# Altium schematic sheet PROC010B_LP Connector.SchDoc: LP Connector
size 431 x 279 mm; Date: Not shown in title block; ApprovedBy: Not shown in title block; CheckedBy: Not shown in title block; Author: Not shown in title block; CompanyName: Not shown in title block; DrawnBy: Adrian Ozer; Engineer: Not shown in title block; Organization: Not shown in title block; Address1: Not shown in title block; Address2: Not shown in title block; Address3: Not shown in title block; Address4: Not shown in title block; DocumentNumber: 11; Revision: Use project parameter SCH_Rev; SheetNumber: 11; SheetTotal: 16; PageSetup: Record=PageOptions¦CenterHorizontal=True¦CenterVertical=True¦PrintScale=1.00¦XCorrection=1.00¦YCorrection=1.00¦PrintKind=0¦BorderSize=5000000¦LeftOffset=0¦BottomOffset=0¦Orientation=2¦PaperLength=1000¦PaperWidth=1000¦Scale=100¦PaperSource=15¦PrintQuality=600¦MediaType=1¦DitherType=10¦PaperKind=Letter¦PrintScaleMode=1
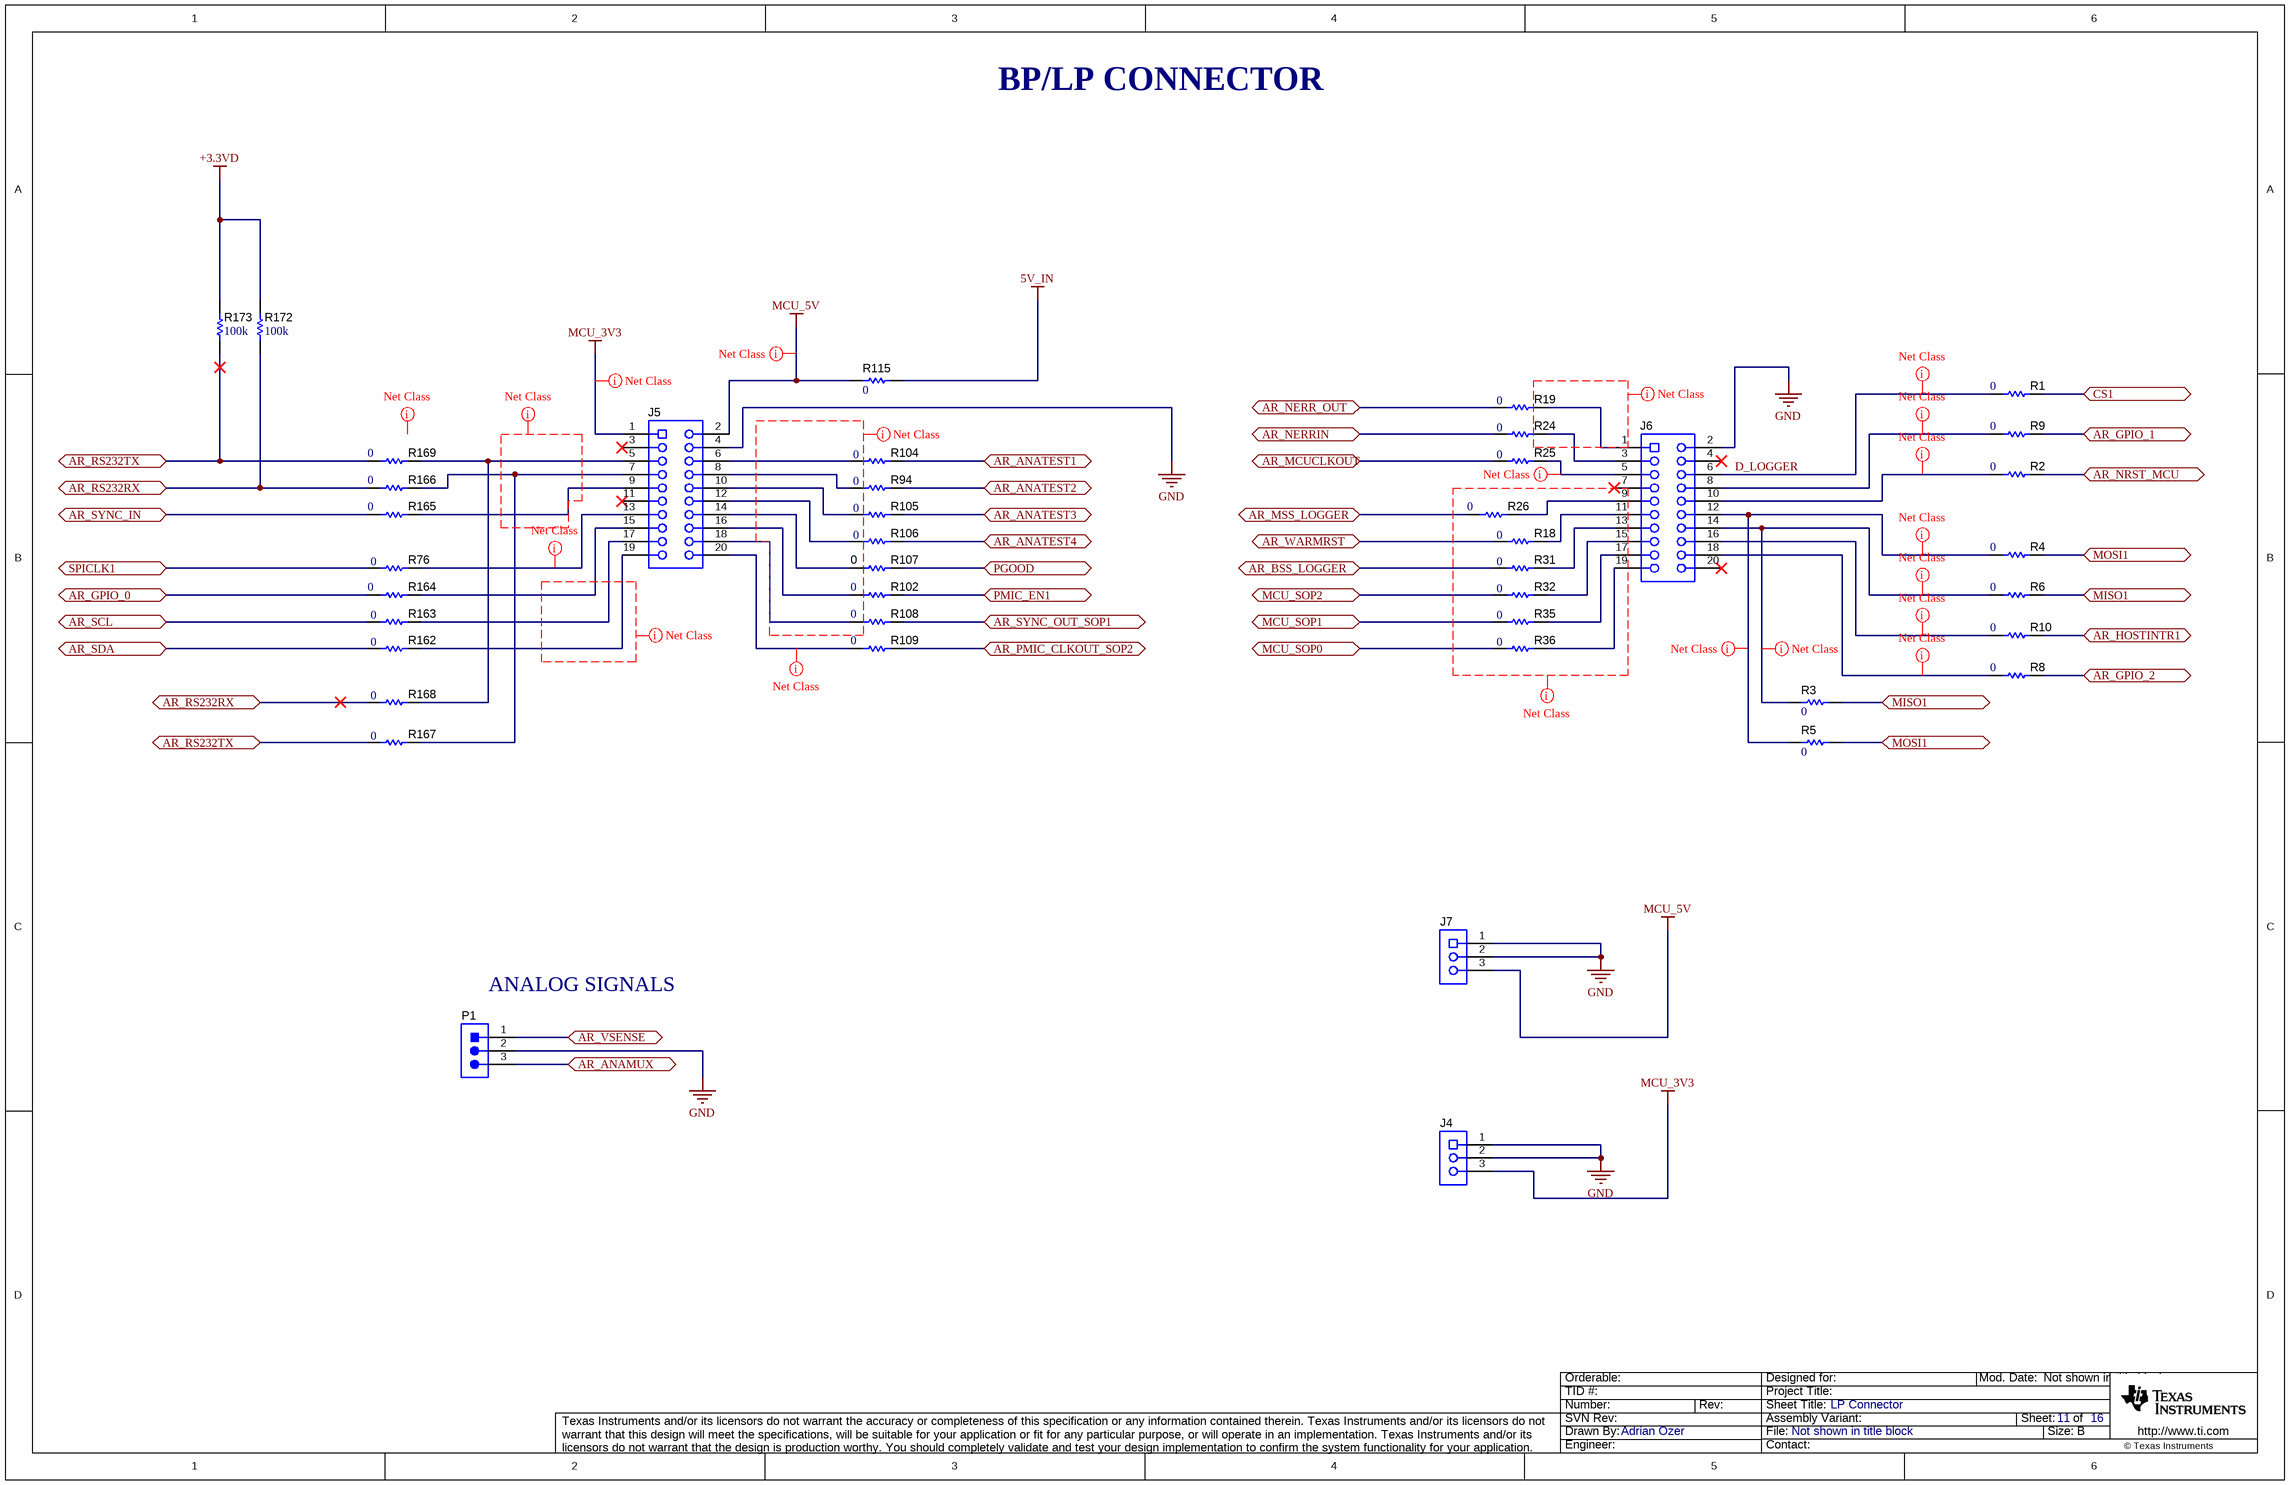
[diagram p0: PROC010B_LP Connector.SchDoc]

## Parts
J4  SSM-103-S-SV  [Samtec_SSM-103-x-SV]  (value not drawn)
J5  SSM-110-S-DV  [Samtec_SSM-110-x-DV]  (value not drawn)
J6  SSM-110-S-DV  [Samtec_SSM-110-x-DV]  (value not drawn)
J7  SSM-103-S-SV  [Samtec_SSM-103-x-SV]  (value not drawn)
P1  TSW-103-07-T-S  [Samtec_TSW-103-07-T-S]  (value not drawn)
R1  ValueDisplayed: 0  [0201_Silk]  (hidden comment: CRCW02010000Z0ED)
R2  ValueDisplayed: 0  [0201_Silk]  (hidden comment: CRCW02010000Z0ED)
R3  ValueDisplayed: 0  [0201_Silk]  (hidden comment: CRCW02010000Z0ED)
R4  ValueDisplayed: 0  [0201_Silk]  (hidden comment: CRCW02010000Z0ED)
R5  ValueDisplayed: 0  [0201_Silk]  (hidden comment: CRCW02010000Z0ED)
R6  ValueDisplayed: 0  [0201_Silk]  (hidden comment: CRCW02010000Z0ED)
R8  ValueDisplayed: 0  [0201_Silk]  (hidden comment: CRCW02010000Z0ED)
R9  ValueDisplayed: 0  [0201_Silk]  (hidden comment: CRCW02010000Z0ED)
R10  ValueDisplayed: 0  [0201_Silk]  (hidden comment: CRCW02010000Z0ED)
R18  ValueDisplayed: 0  [0201_Silk]  (hidden comment: CRCW02010000Z0ED)
R19  ValueDisplayed: 0  [0201_Silk]  (hidden comment: CRCW02010000Z0ED)
R24  ValueDisplayed: 0  [0201_Silk]  (hidden comment: CRCW02010000Z0ED)
R25  ValueDisplayed: 0  [0201_Silk]  (hidden comment: CRCW02010000Z0ED)
R26  ValueDisplayed: 0  [0201_Silk]  (hidden comment: CRCW02010000Z0ED)
R31  ValueDisplayed: 0  [0201_Silk]  (hidden comment: CRCW02010000Z0ED)
R32  ValueDisplayed: 0  [0201_Silk]  (hidden comment: CRCW02010000Z0ED)
R35  ValueDisplayed: 0  [0201_Silk]  (hidden comment: CRCW02010000Z0ED)
R36  ValueDisplayed: 0  [0201_Silk]  (hidden comment: CRCW02010000Z0ED)
R76  ValueDisplayed: 0  [0201_Silk]  (hidden comment: CRCW02010000Z0ED)
R94  ValueDisplayed: 0  [0201_Silk]  (hidden comment: CRCW02010000Z0ED)
R102  ValueDisplayed: 0  [0201_Silk]  (hidden comment: CRCW02010000Z0ED)
R104  ValueDisplayed: 0  [0201_Silk]  (hidden comment: CRCW02010000Z0ED)
R105  ValueDisplayed: 0  [0201_Silk]  (hidden comment: CRCW02010000Z0ED)
R106  ValueDisplayed: 0  [0201_Silk]  (hidden comment: CRCW02010000Z0ED)
R107  ValueDisplayed: 0  [0402L]  (hidden comment: ERJ-2GE0R00X)
R108  ValueDisplayed: 0  [0201_Silk]  (hidden comment: CRCW02010000Z0ED)
R109  ValueDisplayed: 0  [0201_Silk]  (hidden comment: CRCW02010000Z0ED)
R115  ValueDisplayed: 0  [2010]  (hidden comment: CRCW20100000Z0EF)
R162  ValueDisplayed: 0  [0201_Silk]  (hidden comment: CRCW02010000Z0ED)
R163  ValueDisplayed: 0  [0201_Silk]  (hidden comment: CRCW02010000Z0ED)
R164  ValueDisplayed: 0  [0201_Silk]  (hidden comment: CRCW02010000Z0ED)
R165  ValueDisplayed: 0  [0201_Silk]  (hidden comment: CRCW02010000Z0ED)
R166  ValueDisplayed: 0  [0201_Silk]  (hidden comment: CRCW02010000Z0ED)
R167  ValueDisplayed: 0  [0201_Silk]  (hidden comment: CRCW02010000Z0ED)
R168  ValueDisplayed: 0  [0201_Silk]  (hidden comment: CRCW02010000Z0ED)
R169  ValueDisplayed: 0  [0201_Silk]  (hidden comment: CRCW02010000Z0ED)
R172  ValueDisplayed: 100k  [0402L]  (hidden comment: CRCW0402100KFKED)
R173  ValueDisplayed: 100k  [0402L]  (hidden comment: CRCW0402100KFKED)

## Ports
AR_ANAMUX, AR_ANATEST1, AR_ANATEST2, AR_ANATEST3, AR_ANATEST4, AR_BSS_LOGGER, AR_GPIO_0, AR_GPIO_1, AR_GPIO_2, AR_HOSTINTR1, AR_MCUCLKOUT, AR_MSS_LOGGER, AR_NERR_OUT, AR_NERRIN, AR_NRST_MCU, AR_PMIC_CLKOUT_SOP2, AR_RS232RX, AR_RS232TX, AR_SCL, AR_SDA, AR_SYNC_IN, AR_SYNC_OUT_SOP1, AR_VSENSE, AR_WARMRST, CS1, MCU_SOP0, MCU_SOP1, MCU_SOP2, MISO1, MOSI1, PGOOD, PMIC_EN1, SPICLK1

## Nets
5V_IN: R115.2
+3.3VD: R172.2 R173.2
GND: J4.1 J4.2 J5.4 J6.2 J7.1 J7.2 P1.2
MCU_3V3: J4.3 J5.1
MCU_5V: J5.2 J7.3 R115.1
AR_ANAMUX: P1.3 ; port AR_ANAMUX
AR_ANATEST1: R104.2 ; port AR_ANATEST1
AR_ANATEST2: R94.2 ; port AR_ANATEST2
AR_ANATEST3: R105.2 ; port AR_ANATEST3
AR_ANATEST4: R106.2 ; port AR_ANATEST4
AR_BSS_LOGGER: R31.1 ; port AR_BSS_LOGGER
AR_GPIO_0: R164.1 ; port AR_GPIO_0
AR_GPIO_1: R9.2 ; port AR_GPIO_1
AR_GPIO_2: R8.2 ; port AR_GPIO_2
AR_HOSTINTR1: R10.2 ; port AR_HOSTINTR1
AR_MCUCLKOUT: R25.1 ; port AR_MCUCLKOUT
AR_MSS_LOGGER: R26.1 ; port AR_MSS_LOGGER
AR_NERR_OUT: R19.1 ; port AR_NERR_OUT
AR_NERRIN: R24.1 ; port AR_NERRIN
AR_NRST_MCU: R2.2 ; port AR_NRST_MCU
AR_PMIC_CLKOUT_SOP2: R109.2 ; port AR_PMIC_CLKOUT_SOP2
AR_RS232RX: R166.1 R168.1 R172.1 ; port AR_RS232RX
AR_RS232TX: R167.1 R169.1 R173.1 ; port AR_RS232TX
AR_SCL: R163.1 ; port AR_SCL
AR_SDA: R162.1 ; port AR_SDA
AR_SYNC_IN: R165.1 ; port AR_SYNC_IN
AR_SYNC_OUT_SOP1: R108.2 ; port AR_SYNC_OUT_SOP1
AR_VSENSE: P1.1 ; port AR_VSENSE
AR_WARMRST: R18.1 ; port AR_WARMRST
CS1: R1.2 ; port CS1
D_LOGGER: J6.6 R1.1
MCU_SOP0: R36.1 ; port MCU_SOP0
MCU_SOP1: R35.1 ; port MCU_SOP1
MCU_SOP2: R32.1 ; port MCU_SOP2
MISO1: R3.2 R6.2 ; port MISO1
MOSI1: R4.2 R5.2 ; port MOSI1
PGOOD: R107.2 ; port PGOOD
PMIC_EN1: R102.2 ; port PMIC_EN1
SPICLK1: R76.1 ; port SPICLK1
NetJ5_5: J5.5 R168.2 R169.2
NetJ5_6: J5.6 R104.1
NetJ5_7: J5.7 R166.2 R167.2
NetJ5_8: J5.8 R94.1
NetJ5_9: J5.9 R165.2
NetJ5_10: J5.10 R105.1
NetJ5_12: J5.12 R106.1
NetJ5_13: J5.13 R76.2
NetJ5_14: J5.14 R107.1
NetJ5_15: J5.15 R164.2
NetJ5_16: J5.16 R102.1
NetJ5_17: J5.17 R163.2
NetJ5_18: J5.18 R108.1
NetJ5_19: J5.19 R162.2
NetJ5_20: J5.20 R109.1
NetJ6_1: J6.1 R19.2
NetJ6_3: J6.3 R24.2
NetJ6_5: J6.5 R25.2
NetJ6_8: J6.8 R9.1
NetJ6_9: J6.9 R26.2
NetJ6_10: J6.10 R2.1
NetJ6_11: J6.11 R18.2
NetJ6_12: J6.12 R4.1 R5.1
NetJ6_13: J6.13 R31.2
NetJ6_14: J6.14 R3.1 R6.1
NetJ6_15: J6.15 R32.2
NetJ6_16: J6.16 R10.1
NetJ6_17: J6.17 R35.2
NetJ6_18: J6.18 R8.1
NetJ6_19: J6.19 R36.2

Not connected (* = marked no-connect by the designer): J5 3* 11*; J6 4* 7* 20*

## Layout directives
net class GENERAL: (no net found under the mark), NetJ6_8, NetJ6_10, NetJ6_18
net class CLK: NetJ5_20, NetJ6_5
net class PWR: MCU_3V3, MCU_5V
net class SPI: D_LOGGER, NetJ5_13, NetJ6_12, NetJ6_14, NetJ6_16

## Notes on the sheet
- BP/LP CONNECTOR
- (near P1) ANALOG SIGNALS

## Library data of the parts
J4 J7 = CMP-0078183-1: Receptacle, 2.54mm, 3x1, Gold with Tin tail, SMT; Manufacturer: Samtec; Pitch_mm: 2.54; Gender: Female; Cert_CSA: Y; Voltage_V: 405V; Current_A: 5.2A; Row_Count: 1; CompType: Socket Strip
J5 J6 = CMP-0078182-1: Receptacle, 2.54mm, 10x2, Gold with Tin tail, SMT; Manufacturer: Samtec; Pitch_mm: 2.54; Gender: Female; Cert_CSA: Y; Voltage_V: 405V; Current_A: 5.2A; Row_Count: 2; CompType: Socket Strip
P1 = CMP-0075530-2: Header, 2.54 mm, 3x1, Tin, TH; Manufacturer: Samtec; Pitch_mm: 2.54; Cert_VDE: N; Gender: Male; Cert_CSA: Y; Voltage_V: 550V; Green_REACh: Passed; Current_A: 6.3A; Green_Lifecycle: Active; Row_Count: 1
R1-R6 R8-R10 R18 R19 R24-R26 R31 R32 R35 R36 R94 R102 R105 R106 R108 R109 R162-R169 = CMP-0027008-4: RES, 0, 5%, 0.05 W, 0201; Manufacturer: Vishay-Dale; Power_W: 50mW; TempCo: ppm/C; Value_Code: 0000; Value: 0; EIA_Code: E24; SizeX_mm: 0.6; SizeY_mm: 0.3; SizeZ_mm: 0.26; Value2: 0.05W; SizeArea_mm2: 0.18; AEC Qualified: N; AEC Category: Q200
R76 R104 = CMP-0027008-4: RES, 0, 5%, 0.05 W, 0201; Manufacturer: Vishay-Dale; Power_W: 50mW; TempCo: ppm/C; Value_Code: 0000; Value: 0; EIA_Code: E24; SizeX_mm: 0.6; SizeY_mm: 0.3; SizeZ_mm: 0.26; Value2: 0.05W; SizeArea_mm2: 0.18; CompType: Resistor; AEC Qualified: N; AEC Category: Q200
R107 = CMP-0026992-2: RES, 0, 5%, 0.063 W, 0402; Manufacturer: Panasonic; Power_W: 63mW; TempCo: 600 ppm/C; Value_Code: 0000; U/M: EA; Value: 0; EIA_Code: E24; SizeX_mm: 1; SizeY_mm: 0.5; SizeZ_mm: 0.6; Value2: 0.063W; VDC_V: 50V; AEC Category: Q200
R115 = CMP-0016044-3: RES, 0, 5%, 0.75 W, AEC-Q200 Grade 0, 2010; Manufacturer: Vishay-Dale; Power_W: 750mW; TempCo: ppm/C; Value_Code: 0000; Value: 0; EIA_Code: E24; SizeX_mm: 5; SizeY_mm: 2.5; SizeZ_mm: 1.66; Value2: 0.75W; SizeArea_mm2: 12.5; AEC Qualified: Y; AEC Category: Q200
R172 R173 = CMP-0025950-3: RES, 100 k, 1%, 0.063 W, AEC-Q200 Grade 0, 0402; Manufacturer: Vishay-Dale; Power_W: 63mW; TempCo: 100 ppm/C; Value: 100k; EIA_Code: E96; SizeX_mm: 1; SizeY_mm: 0.5; SizeZ_mm: 0.6; Value2: 0.063W; AEC Qualified: Y; VDC_V: 50V; AEC Category: Q200; AEC Grade: 0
